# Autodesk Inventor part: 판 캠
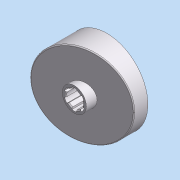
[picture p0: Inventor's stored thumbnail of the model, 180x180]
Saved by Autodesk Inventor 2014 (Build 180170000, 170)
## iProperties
Created: 2012-05
Part Number: 판 캠
Document SubType Name: 모델링
Designer: SeoGD™
Material: 강철
Appearance: 알루미늄 - 평지
Mass: 681.587 g
Surface Area: 331.303 cm^2
Volume: 86.8264 cm^3
Density: 7.85 g/cm^3
변환 표준: STEP AP214IS
파일 이름: C:\Users\SeoGD\Desktop\?쒗뿕\??stp
전처리기: Build: 253, Release: 2010 SP1 - Date: Wed 07/29/2009
전송 단위: 밀리미터
불확실성: 0.01
Author: SeoGD™
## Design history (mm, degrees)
node "작업 평면4"
sketch "스케치1"
  geometry: C1 r 44.5 at (0, 0); 1 further point
  constraints: 1 centre point, 1 coincident
  dimensions: "d25" = 89 diameter of C1
extrude "돌출1" new body sketch "스케치1" distance "d1" = 40; taper "d2" = 0 deg
sketch "스케치2"
  geometry: L1 (-44.5, 15)-(44.5, 38.847); L2 (-44.5, 0)-(-44.5, 40) reference; L3 (-44.5, 40)-(44.5, 40) reference; L4 (44.5, 0)-(44.5, 40) reference; 1 further point
  constraints: 2 end point, 2 point on line
  dimensions: "d26" = 15 distance of L2.start L1.start; "d27" = 75 deg angle of L1 L2
extrude "돌출2" cut sketch "스케치2" stored distance "d5" = 40; taper "d6" = 0 deg
node "작업 평면1"
sketch "스케치3"
  geometry: C1 r 13 at (0, 0); 1 further point
  constraints: 1 centre point, 1 coincident
  dimensions: "d9" = 26 diameter of C1
extrude "돌출3" join sketch "스케치3" distance "d10" = 38; taper "d11" = 0 deg
hole "구멍1" diameter "d14" = 18; stored, may be unused: countersink angle "d18" = 90 deg, drill point angle "d20" = 118 deg; dims "d12" = 10, "d13" = 10, "d15" = 6, "d16" = 4, "d17" = 2, "d19" = 8
feature "쉘2" dims "d29" = 5
sketch "스케치6"
  geometry: C1 r 17.5 at (0, 0); C2 r 14 at (0, 0) reference; 1 further point
  constraints: 1 centre point, 1 coincident
  dimensions: "d28" = 35 diameter of C1
extrude "돌출4" join sketch "스케치6" stored distance "d30" = 38; taper "d31" = 0 deg
fillet "모깎기1" dims "d32" = 3
chamfer "모따기1" distance "d21" = 1; stored, may be unused: second distance "d22" = 2, angle "d23" = 45 deg
sketch "스케치7"
  geometry: L1 (-12.374, 12.374)-(-27.931, 27.931); A1 r 39.5 centre (0, 0) between (-27.931, 27.931) and (0, 39.5) reference; 2 further points
  constraints: 2 end point, 2 point on circle, 1 point on line, 1 vertical alignment, 2 other
  dimensions: "d33" = 45 deg dimension on point (0, 0) L1.start A1.end
feature "리브1" sketch "스케치7" dims "d34" = 5, "d35" = 1, "d36" = 0
fillet "모깎기2" dims "d37" = 3
sketch "스케치8"
  geometry: L1 (2.5, 10.712)-(2.5, 8.646); L2 (-2.5, 10.712)-(-2.5, 8.646); A1 r 11 centre (0, 0) between (2.5, 10.712) and (-2.5, 10.712); A2 r 9 centre (0, 0) between (2.5, 8.646) and (-2.5, 8.646) reference; 1 further point
  constraints: 4 end point, 4 point on circle, 2 parallel, 1 centre point, 1 coincident, 1 vertical
  dimensions: "d41" = 22 diameter of A1; "d42" = 5 distance between parallel lines of L1 L2
extrude "돌출5" cut sketch "스케치8" stored distance "d43" = 38; taper "d44" = 0 deg
fillet "모깎기3" dims "d48" = 1
node "솔리드1"
node "솔리드 본체"
node "곡면 본체"
pattern_circular "원형 패턴1" dims angle "d39" = 360 deg
pattern_circular "원형 패턴2" dims angle "d46" = 360 deg
node "솔리드2"
